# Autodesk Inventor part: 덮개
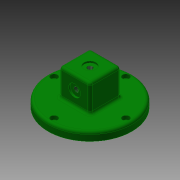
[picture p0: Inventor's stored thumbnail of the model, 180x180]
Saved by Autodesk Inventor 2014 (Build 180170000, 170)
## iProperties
Created: 2017-08
Part Number: 덮개
Material: 알루미늄 6061
Document SubType Name: Modeling
Designer: mduedu
Density: 1 g/cm^3
Appearance: 진녹색
Author: mduedu
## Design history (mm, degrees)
sketch "스케치1"
  geometry: C1 r 49 at (0, 0); 1 further point
  constraints: 1 centre point, 1 coincident
  dimensions: "d55" = 98 diameter of C1
extrude "돌출1" new body sketch "스케치1" distance "d5" = 10; taper "d6" = 0 deg
sketch "스케치2"
  geometry: L1 (-18, -18)-(18, -18); L2 (18, -18)-(18, 18); L3 (18, 18)-(-18, 18); L4 (-18, 18)-(-18, -18); L5 (-18, -18)-(18, 18); L6 (18, -18)-(-18, 18); 1 further point
  constraints: 12 end point, 2 midpoint, 2 parallel, 2 perpendicular, 1 horizontal
  dimensions: "d7" = 36 distance of L2.end L3.end
extrude "돌출2" join sketch "스케치2" distance "d9" = 32; taper "d10" = 0 deg
sketch "스케치3"
  geometry: C1 r 37 at (0, 0); 1 further point
  constraints: 1 centre point, 1 coincident
  dimensions: "d56" = 74 diameter of C1
extrude "돌출3" join sketch "스케치3" distance "d12" = 7; taper "d13" = 0 deg
sketch "스케치4"
  geometry: C1 r 33 at (0, 0); 1 further point
  constraints: 1 centre point, 1 coincident
  dimensions: "d57" = 66 diameter of C1
extrude "돌출4" cut sketch "스케치4" distance "d16" = 6; taper "d17" = 0 deg
sketch "스케치5"
  geometry: C1 r 9 at (0, 0); 1 further point
  constraints: 1 centre point, 1 coincident
  dimensions: "d18" = 18 diameter of C1
extrude "돌출5" cut sketch "스케치5" distance "d19" = 34; taper "d20" = 0 deg
sketch "스케치6"
  geometry: 2 further points
  constraints: 1 coincident
hole "구멍1" sketch "스케치6" at (0, 0) diameter "d21" = 5.917; stored, may be unused: countersink angle "d25" = 90 deg, drill point angle "d27" = 118 deg; dims "d22" = 6, "d23" = 14, "d24" = 2, "d26" = 8
sketch "스케치7"
  geometry: L1 (-31, -10)-(67, -10) reference; 3 further points
  constraints: 1 midpoint, 1 vertical alignment
  dimensions: "d58" = 26 distance from line of point (18, 16) L1
hole "구멍2" sketch "스케치7" at (18, 16) diameter "d29" = 5.917; stored, may be unused: countersink angle "d33" = 90 deg, drill point angle "d35" = 118 deg; dims "d30" = 6, "d31" = 14, "d32" = 2, "d34" = 8
fillet "모깎기2" dims "d37" = 3
fillet "모깎기3" dims "d38" = 3
fillet "모깎기4" dims "d39" = 3
fillet "모깎기5" dims "d40" = 3
chamfer "모따기1" distance "d41" = 1; stored, may be unused: second distance "d42" = 2, angle "d43" = 45 deg
fillet "모깎기7" dims "d45" = 3
fillet "모깎기8" dims "d46" = 3
sketch "스케치10" dims "d59" = 84
  geometry: 3 further points
  constraints: 2 vertical alignment, 1 coincident, 2 other
hole "구멍4" sketch "스케치10" at (0, 42) diameter "d60" = 4.5; stored, may be unused: countersink angle "d64" = 90 deg, drill point angle "d66" = 118 deg; dims "d61" = 6, "d62" = 8, "d63" = 4.6, "d65" = 8
node "솔리드1"
pattern_circular "원형 패턴1" dims angle "d68" = 360 deg
